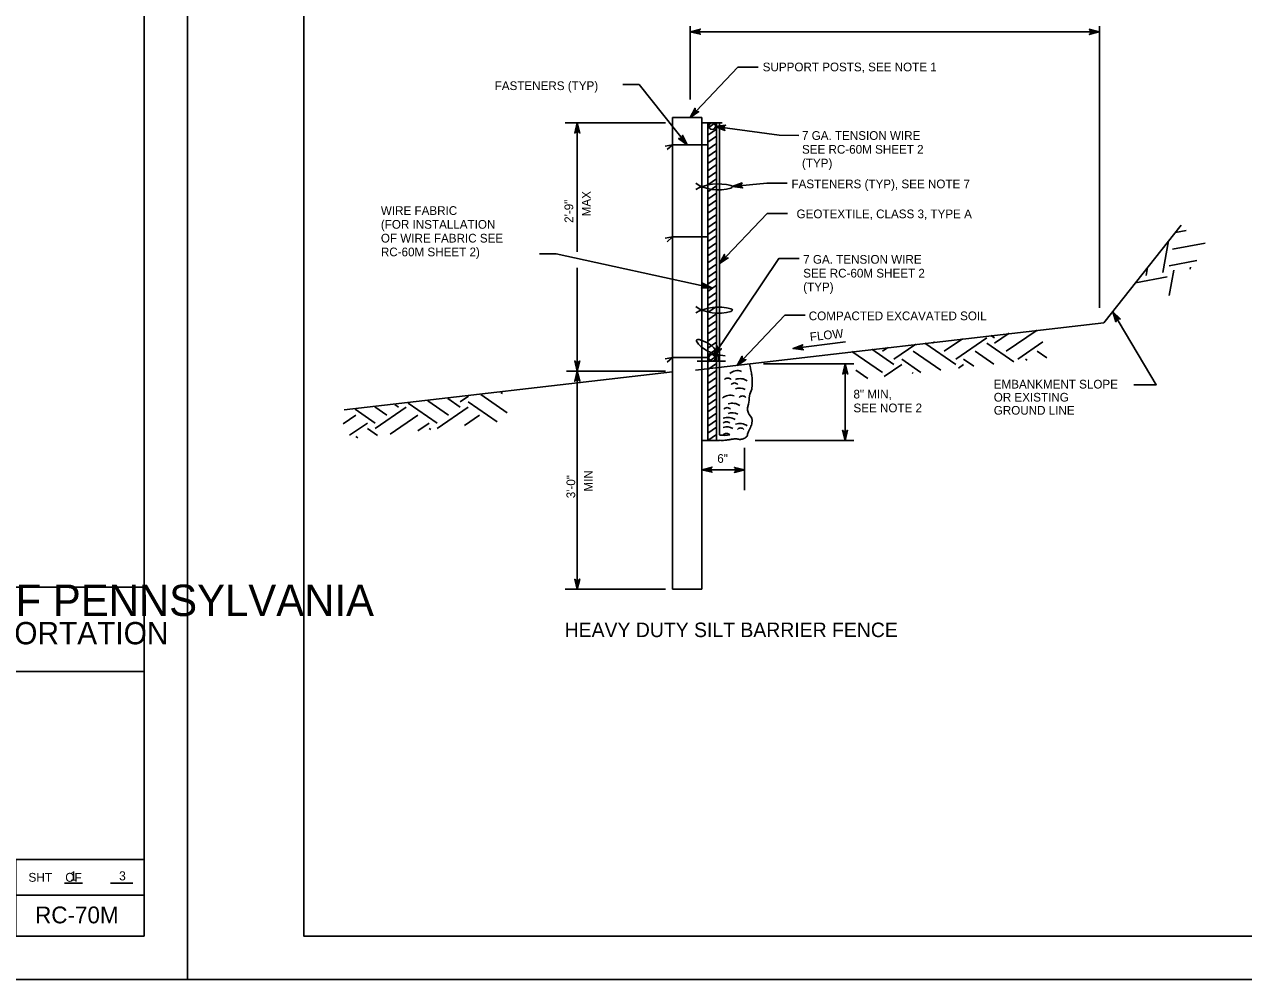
# Model space of a CAD drawing. Extents: x 636462 to 639049, y 299944 to 300538.
# Drawn here: x 637246.7 to 637666.6, y 299944.4 to 300273.2 of the extents above; entities that cross this region are included whole.
import ezdxf

# ---------------------------------------------------------------- set-up
doc = ezdxf.new("R2010")
doc.units = 0
for name, color, linetype in [('1', 7, 'Continuous'), ('Default', 7, 'Continuous'), ('PLT-BNDY', 7, 'Continuous')]:
    doc.layers.add(name, color=color, linetype=linetype)

msp = doc.modelspace()

# ---------------------------------------------------------------- linework, layer by layer
at = {"layer": '1'}
for p, q in [((637260.54, 299977.66), (637266.68, 299977.66)), ((637276.35, 299977.66), (637283.99, 299977.66))]:
    msp.add_line(p, q, dxfattribs=at)
for points in [[(637287.91, 299959.45), (637287.91, 300523.45), (636501.91, 300523.45), (636501.91, 299959.45), (637287.91, 299959.45), (637287.91, 299985.81), (637087.91, 299985.81), (637087.91, 300050.49), (637287.91, 300050.49), (637287.91, 300079.45), (637087.91, 300079.45), (637087.91, 299959.45), (637166.72, 299959.45), (637166.72, 299985.81), (637166.72, 299959.45), (637243.72, 299959.45), (637243.72, 299985.81), (637243.72, 299973.49), (637287.91, 299973.49)], [(638128.91, 299959.45), (638128.91, 300523.45), (637342.91, 300523.45), (637342.91, 299959.45), (638128.91, 299959.45), (638128.91, 299985.81), (637928.91, 299985.81), (637928.91, 300050.49), (638128.91, 300050.49), (638128.91, 300079.45), (637928.91, 300079.45), (637928.91, 299959.45), (638007.72, 299959.45), (638007.72, 299985.81), (638007.72, 299959.45), (638084.72, 299959.45), (638084.72, 299985.81), (638084.72, 299973.49), (638128.91, 299973.49)]]:
    msp.add_lwpolyline(points, dxfattribs=at)
at = {"layer": 'Default'}
for p, q in [((637475.98, 300247.3), (637475.98, 300272.6)), ((637557.31, 300270.66), (637475.98, 300270.66)), ((637616.89, 300175.64), (637616.89, 300272.6)), ((637469.93, 300241.17), (637479.99, 300241.17)), ((637469.93, 300241.17), (637469.93, 300078.76)), ((637479.99, 300241.17), (637479.99, 300078.76)), ((637467.44, 300239.27), (637432.96, 300239.27)), ((637479.99, 300239.27), (637482, 300239.27)), ((637482, 300239.27), (637482, 300130)), ((637482, 300239.27), (637487.03, 300239.27)), ((637482, 300237.49), (637484.59, 300239.27)), ((637482, 300235.05), (637485.02, 300237.12)), ((637485.02, 300239.27), (637485.02, 300130)), ((637486.02, 300239.27), (637486.02, 300132.05)), ((637469.93, 300231.77), (637467.39, 300231.3)), ((637469.93, 300231.77), (637468.01, 300230.09)), ((637469.93, 300231.77), (637482, 300231.77)), ((637482, 300232.61), (637485.02, 300234.68)), ((637482, 300230.16), (637485.02, 300232.24)), ((637482, 300227.72), (637485.02, 300229.79)), ((637482, 300225.28), (637485.02, 300227.35)), ((637482, 300222.84), (637485.02, 300224.91)), ((637482, 300220.39), (637485.02, 300222.47)), ((637482, 300217.95), (637485.02, 300220.02)), ((637482, 300215.51), (637485.02, 300217.58)), ((637482, 300213.07), (637485.02, 300215.14)), ((637482, 300210.62), (637485.02, 300212.7)), ((637482, 300208.18), (637485.02, 300210.25)), ((637482, 300205.74), (637485.02, 300207.81)), ((637482, 300203.3), (637485.02, 300205.37)), ((637482, 300200.85), (637485.02, 300202.93)), ((637618.44, 300170.49), (637645.02, 300204.04)), ((637646.79, 300202.25), (637643.09, 300201.57)), ((637469.93, 300200.06), (637467.39, 300199.59)), ((637469.93, 300200.06), (637468.01, 300198.38)), ((637482, 300200.06), (637469.93, 300200.06)), ((637482, 300198.41), (637485.02, 300200.48)), ((637482, 300195.97), (637485.02, 300198.04)), ((637638.7, 300187.85), (637640.71, 300198.67)), ((637653.29, 300197.93), (637642.03, 300195.84)), ((637482, 300193.53), (637485.02, 300195.6)), ((637482, 300191.08), (637485.02, 300193.16)), ((637482, 300188.64), (637485.02, 300190.71)), ((637632.98, 300186.79), (637633.49, 300189.55)), ((637650.42, 300191.87), (637640.97, 300190.12)), ((637648.13, 300188.99), (637648.25, 300189.63)), ((637482, 300186.2), (637485.02, 300188.27)), ((637482, 300183.76), (637485.02, 300185.83)), ((637640.26, 300186.3), (637629.31, 300184.27)), ((637640.92, 300179.92), (637642.52, 300188.56)), ((637482, 300181.31), (637485.02, 300183.39)), ((637482, 300178.87), (637485.02, 300180.94)), ((637482, 300176.43), (637485.02, 300178.5)), ((637482, 300173.99), (637485.02, 300176.06)), ((637482, 300171.55), (637485.02, 300173.62)), ((637477.74, 300154.15), (637618.44, 300170.49)), ((637482, 300169.1), (637485.02, 300171.18)), ((637482, 300166.66), (637485.02, 300168.73)), ((637482, 300164.22), (637485.02, 300166.29)), ((637563.47, 300160.71), (637569.74, 300165.01)), ((637567.47, 300157.96), (637578.14, 300165.29)), ((637580.81, 300165.29), (637579.55, 300166.15)), ((637580.81, 300163.46), (637585.78, 300166.87)), ((637584.81, 300160.71), (637595.41, 300167.99)), ((637482, 300161.78), (637485.02, 300163.85)), ((637482, 300159.33), (637485.02, 300161.41)), ((637542.14, 300153.38), (637531.64, 300160.59)), ((637546.14, 300156.13), (637538.49, 300161.38)), ((637542.14, 300160.71), (637544.06, 300162.03)), ((637546.14, 300157.96), (637553.69, 300163.15)), ((637562.27, 300154.21), (637552.81, 300160.71)), ((637567.47, 300156.13), (637556.81, 300163.46)), ((637559.47, 300163.46), (637560.11, 300163.89)), ((637580.56, 300156.3), (637574.14, 300160.71)), ((637587.42, 300157.08), (637578.14, 300163.46)), ((637588.81, 300157.96), (637597.43, 300163.88)), ((637598.77, 300158.45), (637595.48, 300160.71)), ((637469.93, 300158.59), (637467.39, 300158.12)), ((637469.93, 300158.59), (637468.01, 300156.9)), ((637482, 300158.59), (637469.93, 300158.59)), ((637478.39, 300157.24), (637488.11, 300157.24)), ((637482, 300156.89), (637485.02, 300158.96)), ((637482, 300154.45), (637485.02, 300156.52)), ((637501.2, 300156.31), (637532.34, 300156.31)), ((637542.77, 300151.98), (637548.81, 300156.13)), ((637555.41, 300153.42), (637548.81, 300157.96)), ((637568.36, 300154.9), (637570.14, 300156.13)), ((637573.7, 300155.51), (637570.14, 300157.96)), ((637592, 300157.6), (637591.48, 300157.96)), ((637356.78, 300140.52), (637469.93, 300153.65)), ((637467.44, 300153.88), (637433.41, 300153.88)), ((637482, 300152.01), (637485.02, 300154.08)), ((637537.11, 300151.34), (637533.01, 300154.15)), ((637552.36, 300153.08), (637552.81, 300153.38)), ((637482, 300149.56), (637485.02, 300151.64)), ((637482, 300147.12), (637485.02, 300149.19)), ((637392.79, 300138.73), (637385.63, 300143.64)), ((637396.79, 300141.47), (637392.48, 300144.44)), ((637396.79, 300143.31), (637399.65, 300145.27)), ((637412.99, 300139.51), (637403.89, 300145.76)), ((637411.36, 300146.13), (637410.73, 300146.55)), ((637482, 300144.68), (637485.02, 300146.75)), ((637482, 300142.24), (637485.02, 300144.31)), ((637367.46, 300135.98), (637360.54, 300140.73)), ((637371.46, 300138.73), (637367.38, 300141.52)), ((637367.46, 300134.15), (637378.12, 300141.47)), ((637375.46, 300141.47), (637374.23, 300142.32)), ((637388.79, 300135.98), (637378.79, 300142.85)), ((637388.79, 300134.15), (637399.46, 300141.47)), ((637409.49, 300136.41), (637399.46, 300143.31)), ((637482, 300139.79), (637485.02, 300141.87)), ((637482, 300137.35), (637485.02, 300139.42)), ((637356.42, 300135.73), (637360.79, 300138.73)), ((637358.69, 300131.79), (637364.79, 300135.98)), ((637372.63, 300132.21), (637382.12, 300138.73)), ((637382.23, 300133.3), (637386.12, 300135.98)), ((637398.22, 300135.13), (637403.46, 300138.73)), ((637482, 300134.91), (637485.02, 300136.98)), ((637361.47, 300130.93), (637360.79, 300131.4)), ((637368.33, 300131.71), (637364.79, 300134.15)), ((637386.62, 300133.8), (637386.12, 300134.15)), ((637482, 300132.47), (637485.02, 300134.54)), ((637482, 300130.02), (637485.02, 300132.1)), ((637486.02, 300130), (637479.99, 300130)), ((637494.69, 300112.94), (637494.69, 300127.46)), ((637498.36, 300130), (637532.34, 300130)), ((637480.03, 300119.89), (637494.4, 300119.89)), ((637467.44, 300078.76), (637432.96, 300078.76)), ((637469.93, 300078.76), (637479.99, 300078.76))]:
    msp.add_line(p, q, dxfattribs=at)
for points in [[(637479.21, 300270.03), (637479.48, 300269.8), (637475.98, 300270.66), (637479.21, 300270.03), (637479.02, 300270.4), (637475.98, 300270.66), (637479.01, 300270.92), (637479.19, 300271.3), (637475.98, 300270.66), (637479.47, 300271.55), (637479.19, 300271.3)], [(637616.89, 300270.66), (637557.31, 300270.66)], [(637613.65, 300271.26), (637613.38, 300271.49), (637616.89, 300270.66), (637613.65, 300271.26), (637613.85, 300270.89), (637616.89, 300270.66), (637613.86, 300270.37), (637613.68, 300269.99), (637616.89, 300270.66), (637613.4, 300269.74), (637613.68, 300269.99)], [(637475.93, 300241.17), (637492.39, 300258.45), (637499.34, 300258.45)], [(637474.87, 300231.77), (637458.39, 300252.47), (637452.72, 300252.47)], [(637478.59, 300243.12), (637478.93, 300243.17), (637475.93, 300241.17), (637478.59, 300243.12), (637478.18, 300243.23), (637475.93, 300241.17), (637477.79, 300243.58), (637477.64, 300243.96), (637475.93, 300241.17), (637477.64, 300244.34), (637477.64, 300243.96)], [(637436.47, 300236.03), (637436.24, 300235.76), (637437.09, 300239.27), (637436.47, 300236.03), (637436.84, 300236.23), (637437.09, 300239.27), (637437.36, 300236.24), (637437.74, 300236.06), (637437.09, 300239.27), (637437.99, 300235.78), (637437.74, 300236.06)], [(637437.09, 300194.89), (637437.09, 300239.27)], [(637487.69, 300236.97), (637487.93, 300236.72), (637484.57, 300238.02), (637487.69, 300236.97), (637487.54, 300237.37), (637484.57, 300238.02), (637487.6, 300237.89), (637487.83, 300238.24), (637484.57, 300238.02), (637488.14, 300238.45), (637487.83, 300238.24)], [(637484.57, 300238.02), (637506.57, 300235.01), (637513.35, 300234.95)], [(637473.35, 300234.69), (637473.35, 300235.04), (637474.87, 300231.77), (637473.35, 300234.69), (637473.18, 300234.31), (637474.87, 300231.77), (637472.77, 300233.98), (637472.37, 300233.88), (637474.87, 300231.77), (637471.99, 300233.94), (637472.37, 300233.88)], [(637493.75, 300217.1), (637494.05, 300216.91), (637490.47, 300217.4), (637493.75, 300217.1), (637493.52, 300217.45), (637490.47, 300217.4), (637493.46, 300217.97), (637493.6, 300218.36), (637490.47, 300217.4), (637493.86, 300218.64), (637493.6, 300218.36)], [(637490.47, 300217.4), (637502.39, 300218.5), (637509.34, 300218.5)], [(637486.02, 300190.86), (637502.48, 300208.14), (637509.43, 300208.14)], [(637483.43, 300182.57), (637429.8, 300194.25), (637424.13, 300194.25)], [(637488.7, 300192.78), (637489.05, 300192.82), (637486.02, 300190.86), (637488.7, 300192.78), (637488.29, 300192.89), (637486.02, 300190.86), (637487.91, 300193.24), (637487.76, 300193.63), (637486.02, 300190.86), (637487.77, 300194.01), (637487.76, 300193.63)], [(637484.05, 300159.13), (637506.49, 300192.59), (637513.44, 300192.59)], [(637437.09, 300153.88), (637437.09, 300189.42)], [(637480.41, 300183.89), (637480.19, 300184.16), (637483.43, 300182.57), (637480.41, 300183.89), (637480.52, 300183.48), (637483.43, 300182.57), (637480.41, 300182.97), (637480.16, 300182.64), (637483.43, 300182.57), (637479.83, 300182.45), (637480.16, 300182.64)], [(637492.13, 300155.83), (637508.6, 300173.11), (637515.54, 300173.11)], [(637621.46, 300174.3), (637636.44, 300149.14), (637628.71, 300149.18)], [(637622.62, 300171.22), (637622.57, 300170.87), (637621.46, 300174.3), (637622.62, 300171.22), (637622.83, 300171.58), (637621.46, 300174.3), (637623.27, 300171.86), (637623.69, 300171.9), (637621.46, 300174.3), (637624.05, 300171.8), (637623.69, 300171.9)], [(637486.4, 300161.44), (637486.73, 300161.53), (637484.05, 300159.13), (637486.4, 300161.44), (637485.98, 300161.48), (637484.05, 300159.13), (637485.54, 300161.77), (637485.34, 300162.14), (637484.05, 300159.13), (637485.29, 300162.51), (637485.34, 300162.14)], [(637511.38, 300161.59), (637529.4, 300163.92)], [(637514.66, 300161.37), (637514.96, 300161.19), (637511.38, 300161.59), (637514.66, 300161.37), (637514.42, 300161.72), (637511.38, 300161.59), (637514.35, 300162.24), (637514.48, 300162.63), (637511.38, 300161.59), (637514.73, 300162.92), (637514.48, 300162.63)], [(637437.72, 300157.12), (637437.94, 300157.39), (637437.09, 300153.88), (637437.72, 300157.12), (637437.34, 300156.92), (637437.09, 300153.88), (637436.82, 300156.91), (637436.45, 300157.09), (637437.09, 300153.88), (637436.19, 300157.38), (637436.45, 300157.09)], [(637494.81, 300157.74), (637495.16, 300157.79), (637492.13, 300155.83), (637494.81, 300157.74), (637494.41, 300157.86), (637492.13, 300155.83), (637494.02, 300158.21), (637493.87, 300158.6), (637492.13, 300155.83), (637493.88, 300158.98), (637493.87, 300158.6)], [(637528.71, 300153.08), (637528.49, 300152.81), (637529.34, 300156.31), (637528.71, 300153.08), (637529.08, 300153.28), (637529.34, 300156.31), (637529.61, 300153.28), (637529.98, 300153.1), (637529.34, 300156.31), (637530.24, 300152.82), (637529.98, 300153.1)], [(637529.34, 300130), (637529.34, 300156.31)], [(637436.45, 300150.65), (637436.23, 300150.38), (637437.09, 300153.88), (637436.45, 300150.65), (637436.83, 300150.85), (637437.09, 300153.88), (637437.35, 300150.85), (637437.72, 300150.67), (637437.09, 300153.88), (637437.98, 300150.39), (637437.72, 300150.67)], [(637436.45, 300150.65), (637436.23, 300150.38), (637437.09, 300153.88), (637436.45, 300150.65), (637436.83, 300150.85), (637437.09, 300153.88), (637437.35, 300150.85), (637437.72, 300150.67), (637437.09, 300153.88), (637437.98, 300150.39), (637437.72, 300150.67)], [(637437.09, 300078.76), (637437.09, 300153.88)], [(637497.27, 300151.01), (637497.35, 300149.1), (637497.14, 300147.62), (637496.5, 300145.93), (637496.29, 300144.66), (637496.29, 300143.81), (637496.08, 300142.54), (637495.66, 300141.27), (637495.66, 300140.42), (637496.08, 300139.36), (637496.29, 300138.94), (637496.72, 300138.3), (637497.14, 300137.67), (637497.27, 300136.82)], [(637529.95, 300133.24), (637530.17, 300133.51), (637529.34, 300130), (637529.95, 300133.24), (637529.58, 300133.04), (637529.34, 300130), (637529.05, 300133.03), (637528.68, 300133.21), (637529.34, 300130), (637528.42, 300133.49), (637528.68, 300133.21)], [(637483.24, 300119.3), (637483.51, 300119.08), (637480.01, 300119.91), (637483.24, 300119.3), (637483.04, 300119.67), (637480.01, 300119.91), (637483.03, 300120.19), (637483.21, 300120.57), (637480.01, 300119.91), (637483.49, 300120.83), (637483.21, 300120.57)], [(637491.44, 300120.52), (637491.17, 300120.74), (637494.67, 300119.91), (637491.44, 300120.52), (637491.64, 300120.15), (637494.67, 300119.91), (637491.65, 300119.63), (637491.47, 300119.25), (637494.67, 300119.91), (637491.19, 300118.99), (637491.47, 300119.25)], [(637437.72, 300082), (637437.94, 300082.27), (637437.09, 300078.76), (637437.72, 300082), (637437.34, 300081.8), (637437.09, 300078.76), (637436.82, 300081.79), (637436.45, 300081.97), (637437.09, 300078.76), (637436.19, 300082.25), (637436.45, 300081.97)]]:
    msp.add_lwpolyline(points, dxfattribs=at)
for centre in [(637483.55, 300238.16), (637483.51, 300158.44)]:
    msp.add_circle(centre, 1.14, dxfattribs=at)
for centre, radius, start, end in [((637492.21, 300150.2), 3.85, 68.5143, 132.7236), ((637488.9, 300149.94), 1.52, 41.6398, 138.3602), ((637491.23, 300148.25), 1.52, 41.6398, 138.3602), ((637493.12, 300146.74), 4.54, 56.3125, 109.4384), ((637492.99, 300144.35), 3.67, 59.0398, 112.1636), ((637489.67, 300141.73), 3.85, 68.5143, 132.7236), ((637493.98, 300143.8), 1.52, 41.6398, 138.3602), ((637488.69, 300139.77), 1.52, 41.6398, 138.3602), ((637490.58, 300138.26), 4.54, 56.3125, 109.4384), ((637490.45, 300135.87), 3.67, 59.0398, 112.1636), ((637488.48, 300134.9), 1.52, 41.6398, 138.3602), ((637488.89, 300133.39), 4.54, 56.3125, 109.4384), ((637493.12, 300131.27), 4.54, 56.3125, 109.4384), ((637486.21, 300132.05), 0.187, 180, 270), ((637487.8, 300144.07), 12.32, 262.5677, 278.7495), ((637488.48, 300130.88), 1.52, 41.6398, 138.3602), ((637488.76, 300131), 3.67, 59.0398, 112.1636), ((637493.35, 300132.79), 1.52, 41.6398, 138.3602)]:
    msp.add_arc(centre, radius, start, end, dxfattribs=at)
for centre, major_axis, start_param, end_param in [((637485.7, 300209.87), (12.27, 0), 1.210381, 2.263588), ((637485.66, 300223.6), (10.76, 0), 3.901169, 5.129116), ((637489.8, 300217.3), (0.683, 0), 5.020961, 7.52504), ((637485.7, 300167.43), (12.27, 0), 1.210381, 2.263588), ((637485.66, 300181.16), (-10.76, 0), 0.759577, 1.987523), ((637489.8, 300174.86), (0.683, 0), 5.020961, 7.52504), ((637478.72, 300164.32), (0.683, 0), 1.078784, 3.582863), ((637475.02, 300157.89), (-10.76, 0), 3.100585, 4.328531), ((637489.36, 300167.47), (-12.27, 0), 0.409796, 1.463003)]:
    msp.add_ellipse(centre, major_axis=major_axis, ratio=0.686052, start_param=start_param, end_param=end_param, dxfattribs=at)
for points in [[(637497.27, 300151.01), (637497.27, 300151.92), (637497.12, 300152.84), (637496.94, 300153.75), (637496.79, 300154.55), (637496.63, 300155.69), (637496.43, 300156.32)], [(637486.07, 300130.04), (637486.49, 300129.99), (637486.92, 300129.96), (637487.34, 300129.99), (637488.49, 300130.09), (637489.64, 300130.33), (637490.79, 300130.48), (637492.01, 300130.63), (637493.28, 300130.19), (637494.48, 300130.71), (637495.58, 300131.18), (637495.78, 300132.52), (637496.27, 300133.57), (637496.67, 300134.44), (637497.15, 300135.27), (637497.24, 300136.19), (637497.26, 300136.4), (637497.27, 300136.61), (637497.27, 300136.82)]]:
    msp.add_open_spline(points, degree=3, dxfattribs=at)
at = {"layer": 'PLT-BNDY'}
for points in [[(636461.91, 300538.45), (637302.91, 300538.45), (637302.91, 299944.45), (636461.91, 299944.45)], [(637302.91, 300538.45), (638143.91, 300538.45), (638143.91, 299944.45), (637302.91, 299944.45)]]:
    msp.add_lwpolyline(points, close=True, dxfattribs=at)

# ---------------------------------------------------------------- texts
at = {"layer": '1'}
for s, height, p in [('COMMONWEALTH OF PENNSYLVANIA', 10.7834, (637101.07, 300069.59)), ('DEPARTMENT OF TRANSPORTATION', 7.6843, (637110.75, 300059.84)), ('SHT    OF', 3.048, (637248.08, 299978.12)), ('1', 3.13, (637262.41, 299978.54)), ('3', 3.13, (637279.28, 299978.59))]:
    msp.add_text(s, height=height, dxfattribs=at).set_placement(p)
at = {"layer": 'Default'}
for s, height, p in [('SUPPORT POSTS, SEE NOTE 1', 2.998, (637500.94, 300257.03)), ('FASTENERS (TYP)', 2.998, (637408.64, 300250.58)), ('7 GA. TENSION WIRE', 2.998, (637514.46, 300233.44)), ('SEE RC-60M SHEET 2', 2.998, (637514.46, 300228.69)), ('(TYP)', 2.998, (637514.46, 300223.94)), ('FASTENERS (TYP), SEE NOTE 7', 2.998, (637510.85, 300216.78)), ('WIRE FABRIC', 2.998, (637369.45, 300207.61)), ('GEOTEXTILE, CLASS 3, TYPE A', 2.998, (637512.6, 300206.47)), ('(FOR INSTALLATION', 2.998, (637369.45, 300202.86)), ('OF WIRE FABRIC SEE', 2.998, (637369.45, 300198.11)), ('RC-60M SHEET 2)', 2.998, (637369.45, 300193.37)), ('7 GA. TENSION WIRE', 2.998, (637514.89, 300190.82)), ('SEE RC-60M SHEET 2', 2.998, (637514.89, 300186.07)), ('(TYP)', 2.998, (637514.89, 300181.33)), ('COMPACTED EXCAVATED SOIL', 2.998, (637516.8, 300171.37)), ('EMBANKMENT SLOPE', 2.998, (637580.51, 300147.87)), ('8" MIN,', 2.998, (637532.19, 300144.44)), ('OR EXISTING', 2.998, (637580.51, 300143.37)), ('SEE NOTE 2', 2.998, (637532.19, 300139.69)), ('GROUND LINE', 2.998, (637580.51, 300138.87)), ('HEAVY DUTY SILT BARRIER FENCE', 4.9967, (637432.74, 300062.32)), ('RC-70M', 5.779, (637250.37, 299963.81))]:
    msp.add_text(s, height=height, dxfattribs=at).set_placement(p)
for s, rotation, p in [('MAX', 90, (637441.68, 300207.12)), ('2\'-9"', 90, (637435.68, 300204.88)), ('FLOW', 6.5142, (637517.35, 300164.12)), ('6"', 360, (637485.29, 300122.29)), ('MIN', 90, (637442.37, 300112.39)), ('3\'-0"', 90, (637436.37, 300110.1))]:
    msp.add_text(s, height=2.998, rotation=rotation, dxfattribs=at).set_placement(p)

doc.saveas('drawing.dxf')
